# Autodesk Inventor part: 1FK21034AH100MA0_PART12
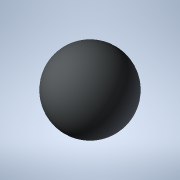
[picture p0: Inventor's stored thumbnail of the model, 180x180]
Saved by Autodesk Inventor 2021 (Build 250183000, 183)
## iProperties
Created: 2025-04
Part Number: 1FK21034AH100MA0_PART12
Material: Generic
Catalog Web Link: www.3dfindit.com
Description: -Servo synchronous motor
Document SubType Name: Modeling
Designer: psAdmin
Mass: 0.113097 g
Surface Area: 1.13097 cm^2
Volume: 0.113097 cm^3
Density: 1 g/cm^3
Appearance: PSOLRGB-212-217-219
Category: PARTsolutions
Title: 1FK21034AH100MA0_PART12
Author: Cadenas PARTsolutions
Comments: Servo synchronous motor
Sending System: PARTsolutions
Preprocessor: ST-DEVELOPER v19.3
PSOL_IDENT_0: {$CADENAS_DATA/23d-libs/siemens_ag/_cat_/39/97/1fk21034ah100ma0.prj},216 {VTYP=3D},{NB=1FK21034AH100
PSOL_IDENT_1: MA0_PART12},{LINA=1FK21034AH100MA0_PART12},{NN=1FK21034AH100MA0_PART12},{NOPRJ=TRUE},{DATE=19.08.202
PSOL_IDENT_2: 5 14:00:33},{GEOMDATE=30.07.2025 02:02:21},{VERSION=},{LINEID=10},{WBVAR=},{WBNUMERIC=}  {NB=1FK2103
PSOL_IDENT_3: 4AH100MA0_PART12},{LINA=1FK21034AH100MA0_PART12},{KT=DUMMY},{PREVIEW=../../../_pool_/d3/78/p_d211_xx
PSOL_IDENT_4: _00934j.png},{DESCSHORT=SIMOTICS S-1FK2 HD, SINAMICS S210 3AC 400V-480V, 1.01 Nm, 4500 rpm},{DESCLON
PSOL_IDENT_5: G=SIMOTICS S-1FK2 HD servo motor M0=1.27 Nm; PN = 0.48 kW at nN=4500 rpm (380-480 V); PN = 0.3 kW at
PSOL_IDENT_6: nN=2500 rpm (200-240 V); with holding brake; degree of protection IP64; cylindrical shaft D14 x 30
PSOL_IDENT_7: mm; absolute encoder 22-bit + 12-bit multiturn (encoder AM22DQC); with OCC interface; plug size M17,
PSOL_IDENT_8: rotatable; SIMOTICS S-1FK2 servomotorfor a wide range of uses in industrial environments. SIMOTICS
PSOL_IDENT_9: S‑1FK2 servomotors are compact synchronous motors with a high dynamic performance that set themselve
PSOL_IDENT_10: s apart as a result of their high power density, degree of protection and overload capability. The m
PSOL_IDENT_11: otors are available in two variants: as High Dynamic variant (highest dynamic performance as a resul
PSOL_IDENT_12: t of the low intrinsic moment of inertia for applications demanding a high dynamic performance with
PSOL_IDENT_13: low moved masses) - and as Compact variant (precise and stable closed-loop control for medium up to
PSOL_IDENT_14: large moved masses as a result of a medium intrinsic moment of inertia). SIMOTICSS‑1FK2 servomotors
PSOL_IDENT_15: fully exploit their strengths in a system with the SINAMICSS210 frequency converter and simple conne
PSOL_IDENT_16: ction using the one cable connection (OCC). Advantages include the short control and positioning tim
PSOL_IDENT_17: es, fast and precise correction of disturbing quantities as well as stable control with a high dynam
PSOL_IDENT_18: ic performance. The servo motors can be configured to address a wide range of requirements. For exam
PSOL_IDENT_19: ple with and without holding brake, IP64 or IP65 degree of protection, singleturn or multiturn absol
PSOL_IDENT_20: ute encoders - to name just a few. Further, the servomotors are available in different shaft heights
PSOL_IDENT_21: extending from 20 to 100. A shaft sealing ring is available to achieve an IP65 degree of protection
PSOL_IDENT_22: and for subsequent mounting at the motor or as spare part. SIMOTICS - the optimum motor for each an
PSOL_IDENT_23: d every motion control application.},{INTNO=195125454019},{SUPPLIERALTNO=1FK2103-4AH10-0MA0},{MANUID=
PSOL_IDENT_24: 1FK21034AH100MA0},{MANUNAME=Siemens},{MANUTYPEDESC=SYNCHRONOUS MOTOR 1FK2 HD 1,27 NM},{AAU732=SIMOTI
PSOL_IDENT_25: CS},{AAO057=S-1FK2},{AAU734=SIMOTICS S-1FK2 HD servo motor M0=1.27 Nm; PN = 0.48 kW at nN=4500 rpm (
PSOL_IDENT_26: 380-480 V); PN = 0.3 kW at nN=2500 rpm (200-240 V); with holding brake; degree of protection IP64; c
PSOL_IDENT_27: ylindrical shaft D14 x 30 mm; absolute encoder 22-bit + 12-bit multiturn (encoder AM22DQC); with OCC
PSOL_IDENT_28: interface; plug size M17, rotatable;},{AAW338=SYNCHRONOUS MOTOR 1FK2 HD 1,27 NM},{AAO742=SIMOTICS},
PSOL_IDENT_29: {AAO663=4034106444921},{NOCUPEROU=1},{PRICEQUANTITY=1},{QUANTITYMIN=1},{QUANTITYINT=1},{CTN=85015100
PSOL_IDENT_30: },{COO=RO},{AAO676=1FK2103-4AH10-0MA0},{AAO677=Siemens AG},{ORDERUNIT=C62},{CONTENTUNIT=C62}
NB: 1FK21034AH100MA0_PART12
NT: Servo synchronous motor
NBSYN: $MANUID._PART12
LINA: 1FK21034AH100MA0_PART12
CATALOG: SIEMENS
PREVIEW: ../../../_pool_/d3/78/p_d211_xx_00934j.png
DESCSHORT: SIMOTICS S-1FK2 HD, SINAMICS S210 3AC 400V-480V, 1.01 Nm, 4500 rpm
DESCLONG: SIMOTICS S-1FK2 HD servo motor M0=1.27 Nm; PN = 0.48 kW at nN=4500 rpm (380-480 V); PN = 0.3 kW at nN=2500 rpm (200-240 V); with holding brake; degree of protec
INTNO: 195125454019
SUPPLIERALTNO: 1FK2103-4AH10-0MA0
MANUID: 1FK21034AH100MA0
MANUNAME: Siemens
MANUTYPEDESC: SYNCHRONOUS MOTOR 1FK2 HD 1,27 NM
AAU732: SIMOTICS
AAO057: S-1FK2
AAU734: SIMOTICS S-1FK2 HD servo motor M0=1.27 Nm; PN = 0.48 kW at nN=4500 rpm (380-480 V); PN = 0.3 kW at nN=2500 rpm (200-240 V); with holding brake; degree of protec
AAW338: SYNCHRONOUS MOTOR 1FK2 HD 1,27 NM
AAO742: SIMOTICS
AAO663: 4034106444921.0
NOCUPEROU: 1
PRICEQUANTITY: 1
QUANTITYMIN: 1
QUANTITYINT: 1
CTN: 85015100
COO: RO
ARTICLENO: 1FK21034AH100MA0_PART12
BOMINFO: 1FK21034AH100MA0_PART12
CREATOR: CADENAS GmbH
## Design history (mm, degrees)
feature "2025_04_17_15_09_00_0361"
body "Solid1"
